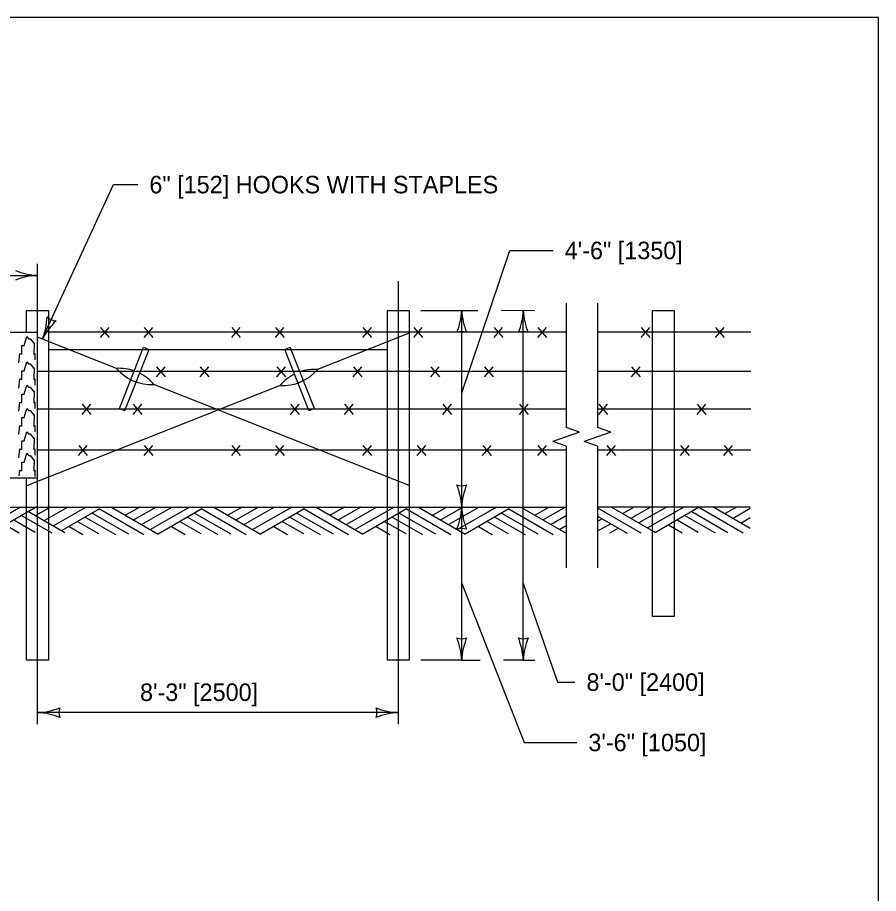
# Model space of a CAD drawing. Extents: x 49991.4 to 50021, y 49987.6 to 50011.4.
# Drawn here: x 50005.661 to 50008.615, y 50008.258 to 50011.263 of the extents above; entities that cross this region are included whole.
import ezdxf

# ---------------------------------------------------------------- set-up
doc = ezdxf.new("R2010")
doc.units = 0
for name, color, linetype in [('Level 1', 7, 'Continuous'), ('Level 2', 7, 'Continuous'), ('Level 3', 7, 'Continuous'), ('Level 4', 7, 'Continuous'), ('Level 5', 7, 'Continuous'), ('Level 6', 7, 'Continuous')]:
    doc.layers.add(name, color=color, linetype=linetype)

msp = doc.modelspace()

# ---------------------------------------------------------------- linework, layer by layer
at = {"layer": 'Level 1'}
for p, q in [((50005.6927, 50010.2583), (50005.7677, 50010.2583)), ((50005.6927, 50010.1834), (50005.6927, 50010.2583)), ((50005.7677, 50010.2583), (50005.7677, 50009.5833)), ((50006.9302, 50010.2583), (50007.0052, 50010.2583)), ((50006.9302, 50009.5833), (50006.9302, 50010.2583)), ((50007.0052, 50010.2583), (50007.0052, 50009.5833)), ((50007.8389, 50009.5833), (50007.8389, 50010.2583)), ((50007.8389, 50010.2583), (50007.9139, 50010.2583)), ((50007.9139, 50010.2583), (50007.9139, 50009.5833)), ((50005.946, 50010.1652), (50005.9753, 50010.1999)), ((50005.9767, 50010.1652), (50005.9473, 50010.1999)), ((50006.096, 50010.1652), (50006.1253, 50010.1999)), ((50006.1267, 50010.1652), (50006.0973, 50010.1999)), ((50006.396, 50010.1652), (50006.4253, 50010.1999)), ((50006.4267, 50010.1652), (50006.3973, 50010.1999)), ((50006.546, 50010.1652), (50006.5753, 50010.1999)), ((50006.5767, 50010.1652), (50006.5473, 50010.1999)), ((50006.846, 50010.1652), (50006.8753, 50010.1999)), ((50006.8767, 50010.1652), (50006.8473, 50010.1999)), ((50007.0204, 50010.1652), (50007.0497, 50010.1999)), ((50007.0511, 50010.1652), (50007.0217, 50010.1999)), ((50007.296, 50010.1652), (50007.3253, 50010.1999)), ((50007.3267, 50010.1652), (50007.2973, 50010.1999)), ((50007.446, 50010.1652), (50007.4753, 50010.1999)), ((50007.4767, 50010.1652), (50007.4473, 50010.1999)), ((50007.8005, 50010.1652), (50007.8298, 50010.1999)), ((50007.8312, 50010.1652), (50007.8018, 50010.1999)), ((50008.0555, 50010.1652), (50008.0848, 50010.1999)), ((50008.0862, 50010.1652), (50008.0568, 50010.1999)), ((50003.3389, 50010.1834), (50005.6927, 50010.1834)), ((50005.6927, 50010.1834), (50005.7302, 50010.1834)), ((50005.7302, 50009.6833), (50005.7302, 50010.1834)), ((50006.0008, 50010.0591), (50005.7302, 50010.1662)), ((50007.5434, 50010.1833), (50005.7677, 50010.1833)), ((50007.0052, 50010.1804), (50006.6901, 50010.0556)), ((50008.1772, 50010.1833), (50007.6513, 50010.1833)), ((50006.0107, 50009.9217), (50006.0939, 50010.1317)), ((50006.0939, 50010.1317), (50006.1125, 50010.1243)), ((50006.5777, 50010.1243), (50006.5963, 50010.1317)), ((50006.6795, 50009.9217), (50006.5963, 50010.1317)), ((50006.9302, 50010.1233), (50005.7677, 50010.1233)), ((50006.0293, 50009.9143), (50006.1125, 50010.1243)), ((50006.661, 50009.9143), (50006.5777, 50010.1243)), ((50007.5434, 50010.0483), (50005.7302, 50010.0483)), ((50006.1381, 50010.0302), (50006.1675, 50010.0649)), ((50006.1688, 50010.0302), (50006.1395, 50010.0649)), ((50006.2881, 50010.0302), (50006.3175, 50010.0649)), ((50006.3188, 50010.0302), (50006.2895, 50010.0649)), ((50006.5506, 50010.0302), (50006.58, 50010.0649)), ((50006.5813, 50010.0302), (50006.552, 50010.0649)), ((50006.8131, 50010.0302), (50006.8425, 50010.0649)), ((50006.8438, 50010.0302), (50006.8145, 50010.0649)), ((50007.0789, 50010.0302), (50007.1082, 50010.0649)), ((50007.1096, 50010.0302), (50007.0802, 50010.0649)), ((50007.2631, 50010.0302), (50007.2925, 50010.0649)), ((50007.2938, 50010.0302), (50007.2645, 50010.0649)), ((50008.1772, 50010.0483), (50007.6513, 50010.0483)), ((50007.7676, 50010.0302), (50007.797, 50010.0649)), ((50007.7983, 50010.0302), (50007.769, 50010.0649)), ((50006.5617, 50010.0005), (50005.6927, 50009.6563)), ((50007.0052, 50009.6574), (50006.1293, 50010.004)), ((50005.8831, 50009.9012), (50005.9125, 50009.9359)), ((50005.9138, 50009.9012), (50005.8845, 50009.9359)), ((50006.0107, 50009.9217), (50006.0293, 50009.9143)), ((50006.0578, 50009.9012), (50006.0872, 50009.9359)), ((50006.0885, 50009.9012), (50006.0592, 50009.9359)), ((50006.598, 50009.9012), (50006.6274, 50009.9359)), ((50006.6287, 50009.9012), (50006.5994, 50009.9359)), ((50006.661, 50009.9143), (50006.6795, 50009.9217)), ((50006.7831, 50009.9012), (50006.8125, 50009.9359)), ((50006.8138, 50009.9012), (50006.7845, 50009.9359)), ((50007.1205, 50009.9012), (50007.1498, 50009.9359)), ((50007.1512, 50009.9012), (50007.1218, 50009.9359)), ((50007.3831, 50009.9012), (50007.4125, 50009.9359)), ((50007.4138, 50009.9012), (50007.3845, 50009.9359)), ((50007.6553, 50009.9012), (50007.6847, 50009.9359)), ((50007.686, 50009.9012), (50007.6567, 50009.9359)), ((50007.9926, 50009.9012), (50008.022, 50009.9359)), ((50008.0233, 50009.9012), (50007.994, 50009.9359)), ((50007.5434, 50009.9193), (50005.7302, 50009.9193)), ((50008.1772, 50009.9193), (50007.6513, 50009.9193)), ((50007.5434, 50009.7783), (50005.7302, 50009.7783)), ((50005.871, 50009.7602), (50005.9003, 50009.7949)), ((50005.9017, 50009.7602), (50005.8723, 50009.7949)), ((50006.096, 50009.7602), (50006.1253, 50009.7949)), ((50006.1267, 50009.7602), (50006.0973, 50009.7949)), ((50006.396, 50009.7602), (50006.4253, 50009.7949)), ((50006.4267, 50009.7602), (50006.3973, 50009.7949)), ((50006.546, 50009.7602), (50006.5753, 50009.7949)), ((50006.5767, 50009.7602), (50006.5473, 50009.7949)), ((50006.846, 50009.7602), (50006.8753, 50009.7949)), ((50006.8767, 50009.7602), (50006.8473, 50009.7949)), ((50007.0325, 50009.7602), (50007.0618, 50009.7949)), ((50007.0632, 50009.7602), (50007.0338, 50009.7949)), ((50007.2568, 50009.7602), (50007.2861, 50009.7949)), ((50007.2875, 50009.7602), (50007.2581, 50009.7949)), ((50007.446, 50009.7602), (50007.4753, 50009.7949)), ((50007.4767, 50009.7602), (50007.4473, 50009.7949)), ((50008.1772, 50009.7783), (50007.6513, 50009.7783)), ((50007.6827, 50009.7602), (50007.712, 50009.7949)), ((50007.7134, 50009.7602), (50007.684, 50009.7949)), ((50007.9355, 50009.7602), (50007.9648, 50009.7949)), ((50007.9662, 50009.7602), (50007.9368, 50009.7949)), ((50008.0847, 50009.7602), (50008.114, 50009.7949)), ((50008.1154, 50009.7602), (50008.086, 50009.7949)), ((50003.3389, 50009.6833), (50005.7302, 50009.6833)), ((50005.6927, 50009.5833), (50005.6927, 50009.6833)), ((50004.5539, 50009.5833), (50007.5434, 50009.5833)), ((50005.6719, 50009.5833), (50005.548, 50009.5117)), ((50005.7249, 50009.5833), (50005.5745, 50009.4964)), ((50005.6992, 50009.5684), (50005.8235, 50009.4966)), ((50005.7742, 50009.5833), (50005.7238, 50009.5542)), ((50005.8338, 50009.5833), (50005.7536, 50009.537)), ((50005.8972, 50009.5833), (50005.7853, 50009.5187)), ((50005.9427, 50009.5776), (50005.813, 50009.5027)), ((50005.9174, 50009.5629), (50006.0417, 50009.4911)), ((50005.9427, 50009.5776), (50006.0945, 50009.4899)), ((50005.9838, 50009.5833), (50006.1438, 50009.4909)), ((50006.0804, 50009.5833), (50006.0321, 50009.5554)), ((50006.1364, 50009.5833), (50006.06, 50009.5393)), ((50006.1917, 50009.5833), (50006.0877, 50009.5233)), ((50006.2507, 50009.5833), (50006.1173, 50009.5062)), ((50006.2938, 50009.5776), (50006.1438, 50009.4909)), ((50006.2685, 50009.5629), (50006.3928, 50009.4911)), ((50006.2938, 50009.5776), (50006.4456, 50009.4899)), ((50006.3349, 50009.5833), (50006.4949, 50009.4909)), ((50006.4315, 50009.5833), (50006.3832, 50009.5554)), ((50006.4875, 50009.5833), (50006.4111, 50009.5393)), ((50006.5428, 50009.5833), (50006.4388, 50009.5233)), ((50006.6018, 50009.5833), (50006.4684, 50009.5062)), ((50006.6449, 50009.5776), (50006.4949, 50009.4909)), ((50006.6196, 50009.5629), (50006.7439, 50009.4911)), ((50006.6449, 50009.5776), (50006.7967, 50009.4899)), ((50006.686, 50009.5833), (50006.846, 50009.4909)), ((50006.7826, 50009.5833), (50006.7343, 50009.5554)), ((50006.8386, 50009.5833), (50006.7622, 50009.5393)), ((50006.8939, 50009.5833), (50006.7899, 50009.5233)), ((50006.9529, 50009.5833), (50006.8195, 50009.5062)), ((50006.996, 50009.5776), (50006.846, 50009.4909)), ((50006.9707, 50009.5629), (50007.095, 50009.4911)), ((50006.996, 50009.5776), (50007.1478, 50009.4899)), ((50007.0371, 50009.5833), (50007.1971, 50009.4909)), ((50007.1337, 50009.5833), (50007.0854, 50009.5554)), ((50007.1897, 50009.5833), (50007.1133, 50009.5393)), ((50007.245, 50009.5833), (50007.141, 50009.5233)), ((50007.304, 50009.5833), (50007.1706, 50009.5062)), ((50007.3471, 50009.5776), (50007.1971, 50009.4909)), ((50007.3218, 50009.5629), (50007.4461, 50009.4911)), ((50007.3471, 50009.5776), (50007.4989, 50009.4899)), ((50007.3882, 50009.5833), (50007.5434, 50009.4937)), ((50007.4848, 50009.5833), (50007.4365, 50009.5554)), ((50007.5408, 50009.5833), (50007.4645, 50009.5393)), ((50008.1746, 50009.5833), (50007.6513, 50009.5833)), ((50007.6513, 50009.5812), (50007.7999, 50009.4954)), ((50007.6987, 50009.5833), (50007.8492, 50009.4964)), ((50007.7762, 50009.5833), (50007.7375, 50009.5609)), ((50007.8323, 50009.5833), (50007.7654, 50009.5448)), ((50007.8875, 50009.5833), (50007.7931, 50009.5288)), ((50007.9466, 50009.5833), (50007.8227, 50009.5117)), ((50007.9996, 50009.5833), (50007.8492, 50009.4964)), ((50007.9739, 50009.5684), (50008.0982, 50009.4966)), ((50007.9988, 50009.5833), (50008.151, 50009.4954)), ((50008.0498, 50009.5833), (50008.1746, 50009.5112)), ((50008.1273, 50009.5833), (50008.0886, 50009.5609)), ((50008.1746, 50009.5782), (50008.1165, 50009.5448)), ((50005.6492, 50009.5396), (50005.7214, 50009.4978)), ((50005.6755, 50009.5548), (50005.7795, 50009.4947)), ((50005.8673, 50009.5341), (50005.9396, 50009.4923)), ((50005.8937, 50009.5493), (50005.9977, 50009.4892)), ((50006.2185, 50009.5341), (50006.2907, 50009.4923)), ((50006.2448, 50009.5493), (50006.3488, 50009.4892)), ((50006.5696, 50009.5341), (50006.6418, 50009.4923)), ((50006.5959, 50009.5493), (50006.6999, 50009.4892)), ((50006.9207, 50009.5341), (50006.9929, 50009.4923)), ((50006.947, 50009.5493), (50007.051, 50009.4892)), ((50007.2718, 50009.5341), (50007.344, 50009.4923)), ((50007.2981, 50009.5493), (50007.4021, 50009.4892)), ((50007.5434, 50009.5529), (50007.4921, 50009.5233)), ((50007.6513, 50009.5527), (50007.7528, 50009.4941)), ((50007.6671, 50009.5436), (50007.6513, 50009.5344)), ((50007.9239, 50009.5396), (50007.9961, 50009.4978)), ((50007.9502, 50009.5548), (50008.0542, 50009.4947)), ((50008.1746, 50009.546), (50008.1445, 50009.5286)), ((50005.6199, 50009.5227), (50005.667, 50009.4954)), ((50005.8381, 50009.5172), (50005.8852, 50009.4899)), ((50006.1892, 50009.5172), (50006.2363, 50009.4899)), ((50006.5403, 50009.5172), (50006.5874, 50009.4899)), ((50006.8914, 50009.5172), (50006.9385, 50009.4899)), ((50007.2425, 50009.5172), (50007.2896, 50009.4899)), ((50007.5434, 50009.5187), (50007.5217, 50009.5062)), ((50007.6967, 50009.5265), (50007.6513, 50009.5003)), ((50007.7231, 50009.5112), (50007.6924, 50009.4935)), ((50007.8946, 50009.5227), (50007.9417, 50009.4954))]:
    msp.add_line(p, q, dxfattribs=at)
msp.add_lwpolyline([(50008.6146, 50011.2628), (50000.3356, 50011.2628), (50000.3356, 50000.0624), (50008.6146, 50000.0624)], close=True, dxfattribs=at)
for points in [[(50005.6659, 50010.0786), (50005.6698, 50010.11), (50005.6757, 50010.1081), (50005.6757, 50010.1375), (50005.6836, 50010.1375), (50005.6934, 50010.1688), (50005.6992, 50010.161), (50005.7051, 50010.161), (50005.7169, 50010.1453), (50005.7189, 50010.1473), (50005.7169, 50010.1081), (50005.7208, 50010.11), (50005.7208, 50010.0884)], [(50005.6659, 50009.9919), (50005.6698, 50010.0233), (50005.6757, 50010.0214), (50005.6757, 50010.0508), (50005.6836, 50010.0508), (50005.6934, 50010.0821), (50005.6992, 50010.0743), (50005.7051, 50010.0743), (50005.7169, 50010.0586), (50005.7189, 50010.0606), (50005.7169, 50010.0214), (50005.7208, 50010.0233), (50005.7208, 50010.0017)], [(50005.6659, 50009.9119), (50005.6698, 50009.9433), (50005.6757, 50009.9414), (50005.6757, 50009.9708), (50005.6836, 50009.9708), (50005.6934, 50010.0021), (50005.6992, 50009.9943), (50005.7051, 50009.9943), (50005.7169, 50009.9786), (50005.7189, 50009.9806), (50005.7169, 50009.9414), (50005.7208, 50009.9433), (50005.7208, 50009.9217)], [(50005.6659, 50009.8319), (50005.6698, 50009.8633), (50005.6757, 50009.8614), (50005.6757, 50009.8908), (50005.6836, 50009.8908), (50005.6934, 50009.9221), (50005.6992, 50009.9143), (50005.7051, 50009.9143), (50005.7169, 50009.8986), (50005.7189, 50009.9006), (50005.7169, 50009.8614), (50005.7208, 50009.8633), (50005.7208, 50009.8417)], [(50005.6659, 50009.7519), (50005.6698, 50009.7833), (50005.6757, 50009.7814), (50005.6757, 50009.8108), (50005.6836, 50009.8108), (50005.6934, 50009.8421), (50005.6992, 50009.8343), (50005.7051, 50009.8343), (50005.7169, 50009.8186), (50005.7189, 50009.8206), (50005.7169, 50009.7814), (50005.7208, 50009.7833), (50005.7208, 50009.7617)], [(50005.6674, 50009.6904), (50005.6698, 50009.7096), (50005.6757, 50009.7077), (50005.6757, 50009.7371), (50005.6836, 50009.7371), (50005.6934, 50009.7684), (50005.6992, 50009.7606), (50005.7051, 50009.7606), (50005.7169, 50009.7449), (50005.7189, 50009.7469), (50005.7169, 50009.7077), (50005.7208, 50009.7096), (50005.7208, 50009.688)]]:
    msp.add_lwpolyline(points, dxfattribs=at)
for centre, start, end in [((50006.0105, 50009.9044), 70.692, 93.5951), ((50006.1196, 50010.1588), 220.0078, 273.5951), ((50006.0105, 50009.9044), 40.0078, 63.2871), ((50006.5713, 50010.1552), 266.4347, 320.0376), ((50006.6805, 50009.9009), 86.4347, 109.12), ((50006.6805, 50009.9009), 116.5245, 140.0376)]:
    msp.add_arc(centre, 0.155, start, end, dxfattribs=at)
at = {"layer": 'Level 3'}
for p, q in [((50005.7464, 50010.1598), (50005.9909, 50010.6896)), ((50005.9909, 50010.6896), (50006.0736, 50010.6896)), ((50005.7302, 50010.2234), (50005.7302, 50010.4183)), ((50003.3389, 50010.3783), (50005.7302, 50010.3783)), ((50007.0452, 50010.2583), (50007.2407, 50010.2583)), ((50007.1851, 50009.5833), (50007.1851, 50010.2583)), ((50007.3207, 50010.2584), (50007.4363, 50010.2583)), ((50007.3963, 50009.0583), (50007.3963, 50010.2583)), ((50007.1851, 50009.0583), (50007.1851, 50009.5833)), ((50007.1851, 50009.0583), (50007.0452, 50009.0583)), ((50007.1851, 50009.0583), (50007.2483, 50009.0583)), ((50007.3963, 50009.0583), (50007.3284, 50009.0583)), ((50007.3963, 50009.0583), (50007.4363, 50009.0583)), ((50006.9677, 50008.8783), (50005.7302, 50008.8783))]:
    msp.add_line(p, q, dxfattribs=at)
for points in [[(50007.1851, 50009.975), (50007.35, 50010.4637), (50007.4983, 50010.4637)], [(50007.1851, 50009.3208), (50007.3995, 50008.7759), (50007.5794, 50008.7759), (50007.5794, 50008.7759)], [(50007.3963, 50009.3213), (50007.5134, 50008.983), (50007.573, 50008.983)]]:
    msp.add_lwpolyline(points, dxfattribs=at)
for centre, radius, start, end in [((50005.7394, 50010.6004), 0.2223, 247.456, 267.6395), ((50005.7417, 50010.1456), 0.233, 92.8273, 112.0772), ((50006.963, 50010.2674), 0.2223, 337.456, 357.6395), ((50007.4178, 50010.2698), 0.233, 182.8273, 202.0772), ((50007.1742, 50010.2675), 0.2223, 337.456, 357.6395), ((50007.629, 50010.2698), 0.233, 182.8273, 202.0772), ((50005.5303, 50010.2469), 0.233, 338.0506, 357.3004), ((50005.9442, 50010.0584), 0.2223, 132.6793, 152.8628), ((50005.8001, 50010.2762), 0.0548, 227.3621, 263.0844), ((50007.1851, 50010.1301), 0.0548, 72.1388, 107.8612), ((50007.3963, 50010.1301), 0.0548, 72.1388, 107.8612), ((50007.1851, 50009.7115), 0.0548, 252.1388, 287.8612), ((50006.9524, 50009.5718), 0.233, 2.8273, 22.0772), ((50007.4072, 50009.5741), 0.2223, 157.456, 177.6395), ((50006.963, 50009.5925), 0.2223, 337.456, 357.6395), ((50007.4178, 50009.5948), 0.233, 182.8273, 202.0772), ((50007.1851, 50009.4551), 0.0548, 72.1388, 107.8612), ((50007.1851, 50009.1865), 0.0548, 252.1388, 287.8612), ((50006.9524, 50009.0468), 0.233, 2.8273, 22.0772), ((50007.4072, 50009.0491), 0.2223, 157.456, 177.6395), ((50007.3963, 50009.1865), 0.0548, 252.1388, 287.8612), ((50007.1635, 50009.0468), 0.233, 2.8273, 22.0772), ((50007.6184, 50009.0491), 0.2223, 157.456, 177.6395), ((50005.7187, 50009.111), 0.233, 272.8273, 292.0772), ((50005.721, 50008.6562), 0.2223, 67.456, 87.6395), ((50005.8584, 50008.8783), 0.0548, 162.1388, 197.8612), ((50006.9769, 50009.1004), 0.2223, 247.456, 267.6395), ((50006.8395, 50008.8783), 0.0548, 342.1388, 17.8612), ((50006.9792, 50008.6456), 0.233, 92.8273, 112.0772)]:
    msp.add_arc(centre, radius, start, end, dxfattribs=at)
at = {"layer": 'Level 4'}
for p, q in [((50005.6927, 50009.0583), (50005.6927, 50009.5833)), ((50005.7677, 50009.5833), (50005.7677, 50009.0583)), ((50006.9302, 50009.0583), (50006.9302, 50009.5833)), ((50007.0052, 50009.5833), (50007.0052, 50009.0583)), ((50007.8389, 50009.2083), (50007.8389, 50009.5833)), ((50007.9139, 50009.5833), (50007.9139, 50009.2083)), ((50007.9139, 50009.2083), (50007.8389, 50009.2083)), ((50005.7677, 50009.0583), (50005.6927, 50009.0583)), ((50007.0052, 50009.0583), (50006.9302, 50009.0583))]:
    msp.add_line(p, q, dxfattribs=at)
at = {"layer": 'Level 5'}
for p, q in [((50005.7302, 50008.8383), (50005.7302, 50010.4183)), ((50006.9677, 50008.8383), (50006.9677, 50010.3583))]:
    msp.add_line(p, q, dxfattribs=at)
at = {"layer": 'Level 6'}
for p, q in [((50007.5434, 50010.2833), (50007.5434, 50009.8569)), ((50007.6513, 50010.2833), (50007.6513, 50009.8569)), ((50007.5891, 50009.8407), (50007.5434, 50009.8569)), ((50007.5891, 50009.8407), (50007.5434, 50009.8245)), ((50007.697, 50009.8407), (50007.6513, 50009.8569)), ((50007.697, 50009.8407), (50007.6513, 50009.8245)), ((50007.5434, 50009.8245), (50007.4977, 50009.8083)), ((50007.5434, 50009.7921), (50007.4977, 50009.8083)), ((50007.6513, 50009.8245), (50007.6056, 50009.8083)), ((50007.6513, 50009.7921), (50007.6056, 50009.8083)), ((50007.5434, 50009.7921), (50007.5434, 50009.3745)), ((50007.6513, 50009.7921), (50007.6513, 50009.3745))]:
    msp.add_line(p, q, dxfattribs=at)

# ---------------------------------------------------------------- texts
at = {"layer": 'Level 2'}
for s, p in [('6" [152] HOOKS WITH STAPLES', (50006.1136, 50010.6596)), ('4\'-6" [1350]', (50007.5383, 50010.4337)), ('8\'-0" [2400]', (50007.613, 50008.953)), ('8\'-3" [2500]', (50006.0815, 50008.9183)), ('3\'-6" [1050]', (50007.6194, 50008.7459))]:
    msp.add_text(s, height=0.06, dxfattribs=at).set_placement(p)

doc.saveas('drawing.dxf')
